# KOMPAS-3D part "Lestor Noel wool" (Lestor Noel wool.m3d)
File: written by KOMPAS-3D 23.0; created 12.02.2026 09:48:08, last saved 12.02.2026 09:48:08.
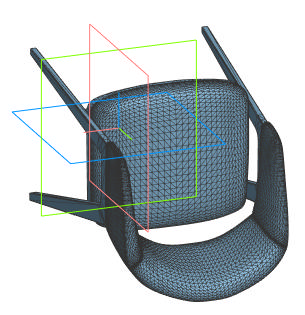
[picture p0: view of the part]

Document properties: Автор: MasterVerators; Полное имя файла: Z:\КомОтдел\Фото и Видео\3D модели\Деревянные стулья и столы\Lestor\Lestor Noel wool\Lestor Noel wool.m3d

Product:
- Part/product: Lestor Noel wool

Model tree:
1. Полигональный объект:1  (labels: Object002)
